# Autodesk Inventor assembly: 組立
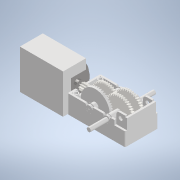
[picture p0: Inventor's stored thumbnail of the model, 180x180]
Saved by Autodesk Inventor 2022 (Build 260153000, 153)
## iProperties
Created: 2024-12
Part Number: 組立
Document SubType Name: Assembly
Designer: jsat7
Author: jsat7
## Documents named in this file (15)
- C:\Users\jsat7\OneDrive\デスクトップ\CAD 長田\組立.iam
- C:\Users\jsat7\OneDrive\デスクトップ\CAD 長田\ボックス　下.ipt
- C:\Users\jsat7\OneDrive\デスクトップ\CAD 長田\B3.ipt
- C:\Users\jsat7\OneDrive\デスクトップ\CAD 長田\2段平ギア.iam
- C:\Users\jsat7\OneDrive\デスクトップ\CAD 長田\B4.ipt
- C:\Users\jsat7\OneDrive\デスクトップ\CAD 長田\B6.ipt
- C:\Users\jsat7\OneDrive\デスクトップ\CAD 長田\丸棒.ipt
- C:\Users\jsat7\OneDrive\デスクトップ\CAD 長田\クラウンギア.iam
- C:\Users\jsat7\OneDrive\デスクトップ\CAD 長田\モーター　ピニオンギア.iam
- C:\Users\jsat7\OneDrive\デスクトップ\CAD 長田\モーター　箱.ipt
- C:\Users\jsat7\OneDrive\デスクトップ\CAD 長田\ピニオンギア.ipt
- C:\Users\jsat7\OneDrive\デスクトップ\CAD 長田\特殊平ギア.ipt
- C:\Users\jsat7\OneDrive\デスクトップ\CAD 長田\六角シャフト.ipt
- C:\Users\jsat7\OneDrive\デスクトップ\CAD 長田\固定器具.ipt
- C:\Users\jsat7\OneDrive\デスクトップ\CAD 長田\B7.ipt
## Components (13 placed, 11 different names)
1. B4:1 — メイト:2, フラッシュ:2, メイト:3
2. B6:1 — メイト:1, メイト:28, メイト:29, フラッシュ:13
3. 丸棒:1 — メイト:3, メイト:5, メイト:20, メイト:28
4. クラウンギア:1 [sub-assembly] — メイト:5, メイト:22, 回転:1, 回転:2, メイト:29
5. モーター　ピニオンギア:1 [sub-assembly] — フラッシュ:5, フラッシュ:6, メイト:13, メイト:14, フラッシュ:8
6. 平歯車1:1 — メイト:14, フラッシュ:8, 回転:1, 角度:1
7. 平歯車1:2 — リジッド:1, メイト:23, 回転:4
8. 六角シャフト:1 — リジッド:1, リジッド:2, メイト:21, メイト:26
9. 固定器具:1 — リジッド:2, メイト:27
10. 2段平ギア:1 [sub-assembly] — メイト:20, メイト:22, 回転:3, 回転:4
11. 2段平ギア:2 [sub-assembly] — メイト:21, メイト:23, 回転:2, 回転:3
12. B3:1 — メイト:24, フラッシュ:11
13. B7:1 — メイト:25, フラッシュ:12, メイト:26, メイト:27
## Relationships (30: Mate 16, Flush 7, RelateRotation 4, WeldJoint 2, Angle 1)
- メイト:1 [Mate]: B6:1
- メイト:2 [Mate]: B4:1
- フラッシュ:2 [Flush]: B4:1
- メイト:3 [Mate]: B4:1 ↔ 丸棒:1
- メイト:5 [Mate]: 丸棒:1 ↔ クラウンギア:1
- フラッシュ:5 [Flush]: モーター　ピニオンギア:1
- フラッシュ:6 [Flush]: モーター　ピニオンギア:1
- メイト:13 [Mate]: モーター　ピニオンギア:1
- メイト:14 [Mate]: モーター　ピニオンギア:1 ↔ 平歯車1:1
- フラッシュ:8 [Flush]: モーター　ピニオンギア:1 ↔ 平歯車1:1
- リジッド:1 [WeldJoint]: 平歯車1:2 ↔ 六角シャフト:1
- リジッド:2 [WeldJoint]: 六角シャフト:1 ↔ 固定器具:1
- メイト:20 [Mate]: 丸棒:1 ↔ 2段平ギア:1
- メイト:21 [Mate]: 六角シャフト:1 ↔ 2段平ギア:2
- メイト:22 [Mate]: クラウンギア:1 ↔ 2段平ギア:1
- メイト:23 [Mate]: 平歯車1:2 ↔ 2段平ギア:2
- 回転:1 [RelateRotation]: クラウンギア:1 ↔ 平歯車1:1
- 回転:2 [RelateRotation]: クラウンギア:1 ↔ 2段平ギア:2
- 回転:3 [RelateRotation]: 2段平ギア:1 ↔ 2段平ギア:2
- 回転:4 [RelateRotation]: 平歯車1:2 ↔ 2段平ギア:1
- 角度:1 [Angle]: 平歯車1:1
- メイト:24 [Mate]: B3:1
- フラッシュ:11 [Flush]: B3:1
- メイト:25 [Mate]: B7:1
- フラッシュ:12 [Flush]: B7:1
- メイト:26 [Mate]: 六角シャフト:1 ↔ B7:1
- メイト:27 [Mate]: 固定器具:1 ↔ B7:1
- メイト:28 [Mate]: B6:1 ↔ 丸棒:1
- メイト:29 [Mate]: B6:1 ↔ クラウンギア:1
- フラッシュ:13 [Flush]: B6:1
